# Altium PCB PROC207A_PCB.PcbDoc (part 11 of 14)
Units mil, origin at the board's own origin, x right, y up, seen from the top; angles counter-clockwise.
Board outline 4094.49 x 3724.79 mil, 8 copper layers (Top Layer, L2_GND1, L3_SIG1, L4_PWR1, L5_PWR2, L6_SIG2, L7_GND2, Bottom Layer), stack 58.1 mil thick; 584 components, 399 nets, 8440 pads, 5258 vias.
Unrouted connection lines stored in the file: 9.
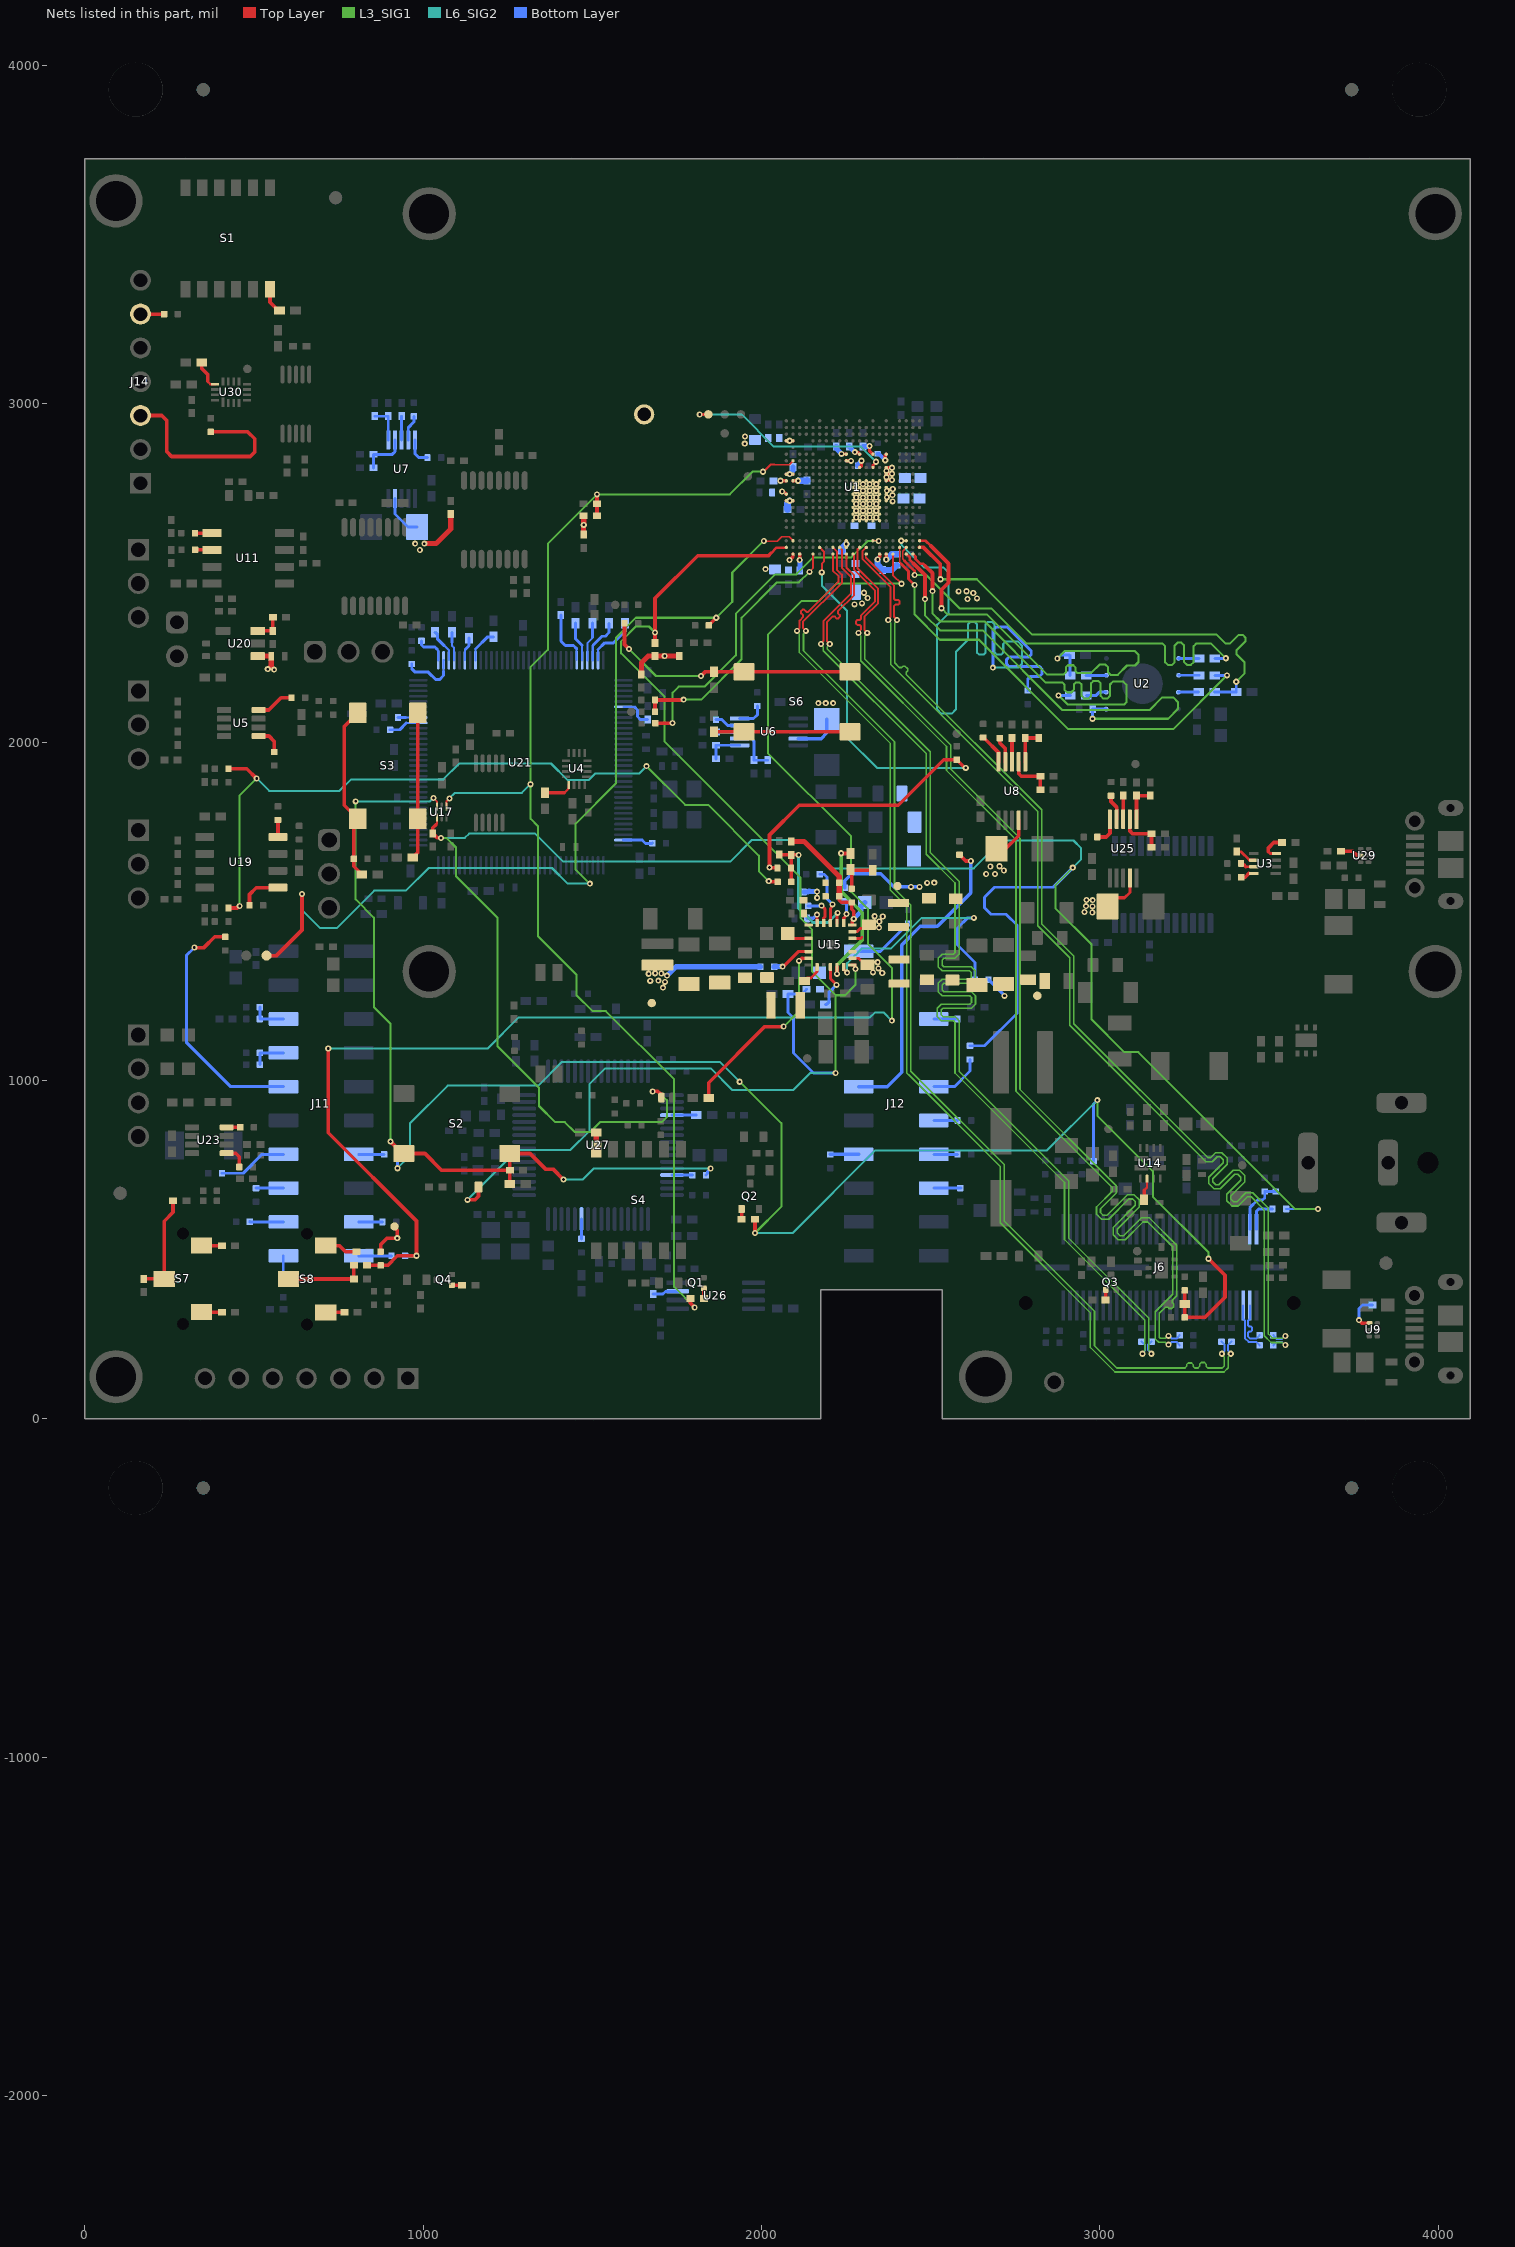
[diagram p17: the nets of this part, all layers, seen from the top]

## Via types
v1: diameter 13.77, hole 7, Top Layer to L2_GND1, tented top, 4306 vias
v2: diameter 18, hole 8, Top Layer to Bottom Layer, tented both sides, 946 vias
v3: diameter 19.68, hole 8, Top Layer to Bottom Layer, tented both sides, 6 vias

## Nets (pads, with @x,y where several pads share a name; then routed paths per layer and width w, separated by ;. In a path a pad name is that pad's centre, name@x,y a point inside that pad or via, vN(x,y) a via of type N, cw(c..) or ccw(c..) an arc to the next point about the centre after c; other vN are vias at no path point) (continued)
NetJ6_56: J6.56 R229.1 | length 151
  Bottom Layer w5.9: J6.56@3423.75,334.85 3423.75,295.66 3428.69,290.72 3428.69,238.82 3440.09,227.43 3463.01,227.43 3472.47,217.98 R229.1@3472.47,217.48
NetJ6_57: J6.57 R62.2 R153.1 | length 171.3
  Bottom Layer w8.7: J6.57@3443.44,560.44 3443.44,623.86 3466.07,646.5 3480.99,646.5 3487.69,653.2 R62.2@3487.69,672.07 R153.1@3520.34,672.07
NetJ6_58: J6.58 R230.1 | length 150.4
  Bottom Layer w5.9: J6.58@3443.44,334.85 3443.44,295.66 3438.49,290.72 3438.49,276.29 3442.3,272.48 3447.02,272.48 3450.48,269.03 3450.48,262.16 3447.02,258.7 3441.95,258.7 3438.49,255.25 3438.49,242.88 3444.15,237.23 3463.01,237.23 3472.47,246.68 R230.1@3472.47,247.17
NetJ6_59: J6.59 R63.2 | length 103.6
  Bottom Layer w8.7: J6.59@3463.12,560.44 3463.12,613.96 3469.67,620.51 R63.2@3510.52,620.51
NetJ11_5: J11.5 R176.2 R180.2 | length 105
  Bottom Layer w8.7: R180.2@517.05,1217 R176.2@517.05,1182 J11.5@587.05,1182
NetJ11_7: J11.7 R178.2 R198.2 | length 105
  Bottom Layer w8.7: R198.2@517.05,1047 R178.2@517.05,1082 J11.7@587.05,1082
NetJ11_9: J11.9 R254.2 | length 735.6
  Top Layer w10.8: v2(323.54,1393.06) 351.97,1393.06 383.64,1424.73 R254.2@414.56,1424.73
  Bottom Layer w8.7: v2(323.54,1393.06) 299.81,1369.33 299.81,1112.89 430.71,982 J11.9@587.05,982
NetJ11_13: J11.13 R210.2 | length 205.2
  Bottom Layer w8.7: R210.2@405,726 467.71,726 523.71,782 J11.13@587.05,782
NetJ11_14: J11.14 R211.1 | length 75
  Bottom Layer w8.7: J11.14@809.49,782 R211.1@884.49,782
NetJ11_15: J11.15 R222.2 | length 81.2
  Bottom Layer w8.7: R222.2@505.82,682 J11.15@587.05,682
NetJ11_17: J11.17 R224.2 | length 100.2
  Bottom Layer w8.7: R224.2@487.18,582.78 487.96,582 J11.17@587.05,582
NetJ11_18: J11.18 R232.1 | length 70
  Bottom Layer w8.7: J11.18@809.49,582 R232.1@879.49,582
NetJ11_19: J11.19 R238.2 | length 82.6
  Bottom Layer w6: J11.19@586.27,481.22 J11.19@587.05,482
  Bottom Layer w8.7: R238.2@586.27,399.73 J11.19@586.27,481.22
NetJ11_20: J11.20 R240.1 | length 96.6
  Bottom Layer w8.7: J11.20@809.49,482 R240.1@906.04,482
NetJ12_1: J12.1 R175.2 | length 180.9
  Bottom Layer w8.7: J12.1@2287.05,1382 2351.96,1382 R175.2@2433.97,1464.01
NetJ12_6: J12.6 R177.1 | length 70
  Bottom Layer w8.7: J12.6@2509.49,1182 R177.1@2579.49,1182
NetJ12_9: J12.9 R182.2 | length 925.3
  Top Layer w10.8: R182.2@2585.42,1667.27 2585.92,1667.27 2589.87,1663.32 2589.87,1662.83 2603.76,1648.94 v2(2618.76,1648.94)
  Bottom Layer w10: J12.9@2287.05,982 2372,982 2414,1024 2414,1400.75 2469.11,1455.85 2520.19,1455.85 2618.76,1554.43 v2(2618.76,1648.94)
NetJ12_10: J12.10 R183.1 | length 160.2
  Bottom Layer w8.7: J12.10@2509.49,982 2570.12,982 2616.19,1028.07 R183.1@2616.19,1062.44
NetJ12_12: J12.12 R201.1 | length 70
  Bottom Layer w8.7: J12.12@2509.49,882 R201.1@2579.49,882
NetJ12_13: J12.13 R212.2 | length 84.1
  Bottom Layer w10: R212.2@2202.92,782 J12.13@2287.05,782
NetJ12_14: J12.14 R221.1 | length 70
  Bottom Layer w8.7: J12.14@2509.49,782 R221.1@2579.49,782
NetJ12_16: J12.16 R223.1 | length 79.6
  Bottom Layer w8.7: J12.16@2509.49,682 R223.1@2589.11,682
NetJ14_3: J14.3 R285.1 | length 624.5
  Top Layer w10.8: J14.3@164.17,2965.75 226.8,2965.75 242.34,2950.2 242.34,2858.47 256.15,2844.66 488.43,2844.66 501.75,2857.98 501.75,2897.18 481.5,2917.43 R285.1@371.87,2917.43
NetJ14_6: J14.6 R286.1 | length 70
  Top Layer w10.8: J14.6@164.17,3265.75 R286.1@234.17,3265.75
NetQ1_1: Q1.1 R171.1 | length 30
  Top Layer w10.8: R171.1@1829.27,355.83 Q1.1@1829.27,385.83
NetQ2_1: Q2.1 R179.2 | length 30
  Top Layer w10.8: R179.2@1941.38,590.43 Q2.1@1941.38,620.43
NetQ3_1: Q3.1 R263.1 | length 30
  Top Layer w10.8: R263.1@3017.23,351.35 Q3.1@3017.23,381.35
NetQ4_1: Q4.1 R66.1 | length 30
  Top Layer w10.8: Q4.1@1084.87,394.98 R66.1@1114.87,394.98
NetR2_1: R2.1 R101.2 U6.2 | length 141.9
  Bottom Layer w8.7: U6.2@1935.43,2010.83 1970.16,2010.83 1978.01,2002.98 R2.1@1978.01,1946.88 R101.2@2018.01,1946.88
NetR6_2: R6.2 U4.13 | length 85.7
  Top Layer w7: 1416.83,1850.39 1430.12,1863.68 U4.13@1430.12,1874.02
  Top Layer w10.8: R6.2@1360.24,1850.39 1416.83,1850.39
NetR13_2: R13.2 R203.2 S7.2 | length 301.7
  Top Layer w10.8: R203.2@174.2,413.65 S7.2@234.2,413.65 234.2,584.26 260.32,610.38 R13.2@260.32,644.49
NetR14_1: R14.1 R103.2 U6.1 | length 110
  Bottom Layer w8.7: R103.2@1865.43,1951.15 R14.1@1865.43,1991.15 U6.1@1935.43,1991.15
NetR16_2: R16.2 R206.2 S8.2 | length 232.8
  Top Layer w10.8: S8.2@601.65,413.28 R16.2@794.44,413.28 ; R16.2@794.73,413.57 R206.2@794.73,453.57
NetR18_2: R18.2 U23.1 | length 71.7
  Top Layer w10.8: U23.1@419.13,785.14 445.72,785.14 456.19,774.67 R18.2@456.19,744.34
NetR19_2: R19.2 U23.4 | length 40
  Top Layer w10.8: U23.4@419.13,861.92 R19.2@459.13,861.92
NetR25_1: R25.1 U6.5 | length 82.9
  Bottom Layer w8.7: U6.5@1935.43,2069.89 1976.5,2069.89 1987.58,2080.97 R25.1@1987.58,2107.09
NetR29_1: R29.1 U6.4 | length 76.6
  Bottom Layer w8.7: R29.1@1865.69,2066.72 1882.8,2066.72 1899.32,2050.2 U6.4@1935.43,2050.2
NetR33_2: R33.2 U14.10 | length 66
  Top Layer w7: 3130.93,675.21 3139.35,683.63 U14.10@3139.35,709.79
  Top Layer w10.8: R33.2@3130.93,647.27 3130.93,675.21
NetR45_1: R45.1 U2.5 | length 60
  Bottom Layer w8.7: U2.5@3233.08,2248 R45.1@3293.08,2248
NetR46_2: R46.2 U2.2 | length 62.6
  Bottom Layer w8.7: R46.2@2960.1,2138.79 2989.49,2138.79 2998.7,2148 U2.2@3018.92,2148
NetR47_2: R47.2 U2.3 | length 60
  Bottom Layer w8.7: R47.2@2959.7,2198 U2.3@3019.7,2198
NetR48_1: R48.1 U2.6 | length 60
  Bottom Layer w8: U2.6@3233.08,2198 R48.1@3293.08,2198
NetR51_1: R51.1 U2.7 | length 60
  Bottom Layer w8.7: U2.7@3232.3,2148 R51.1@3292.3,2148
NetR55_1: R55.1 U3.8 | length 41.8
  Top Layer w9: 3440.42,1611.98 U3.8@3455.43,1611.98
  Top Layer w10.8: R55.1@3418.12,1601.14 3429.59,1601.14 3440.42,1611.98
NetR56_1: R56.1 U3.7 | length 42.4
  Top Layer w7: 3431.61,1631.66 U3.7@3455.43,1631.66
  Top Layer w10.8: R56.1@3417.52,1641.74 3417.52,1641.25 3421.47,1637.3 3425.98,1637.3 3431.61,1631.66
NetR70_1: R70.1 S4.12 | length 50
  Top Layer w15: S4.12@1511.51,796.87 R70.1@1511.51,846.87
NetR72_2: R72.2 U9.1 | length 114.6
  Top Layer w10.8: v2(3766.12,291.81) 3775.03,282.9 U9.1@3797.71,282.9
  Bottom Layer w8.7: v2(3766.12,291.81) 3766.12,326.34 3776.41,336.63 R72.2@3806.64,336.63
NetR76_2: R76.2 R83.1 R84.2 | length 124.6
  Top Layer w10.8: R83.1@2266.3,1566.9 2266.3,1621.21 R76.2@2263.5,1624.01 2265.96,1621.55 R84.2@2328.82,1621.55
NetR78_2: R78.2 U5.1 | length 83.8
  Top Layer w10.8: U5.1@513.63,2018.47 543.83,2018.47 559.82,2002.47 R78.2@559.82,1971.44
NetR80_2: R80.2 U5.4 | length 112.3
  Top Layer w10.8: U5.4@513.63,2095.24 543.24,2095.24 579.85,2131.85 R80.2@610.72,2131.85
NetR82_1: R82.1 R86.2 U20.3 | length 85
  Top Layer w10.8: U20.3@510.67,2329.21 R86.2@555.67,2329.21 R82.1@555.67,2369.21
NetR94_2: R94.2 U6.3 | length 70
  Bottom Layer w8.7: R94.2@1865.43,2030.52 U6.3@1935.43,2030.52
NetR104_1: R104.1 R113.2 U7.2 | length 141.9
  Bottom Layer w8.7: R104.1@852.43,2811.18 R113.2@852.43,2851.18 908.52,2851.18 916.37,2859.03 U7.2@916.37,2893.76
NetR105_1: R105.1 R114.2 U7.1 | length 110
  Bottom Layer w8.7: R114.2@856.69,2963.76 884.08,2963.76 R105.1@896.69,2963.76 U7.1@896.69,2893.76
NetR106_1: R106.1 R116.2 U8.2 | length 141.9
  Top Layer w10.8: U8.2@2760.16,1942.5 2760.16,1907.77 2768.01,1899.92 R106.1@2824.11,1899.92 R116.2@2824.11,1859.92
NetR107_1: R107.1 R117.2 U8.1 | length 110
  Top Layer w10.8: U8.1@2779.84,1942.5 R107.1@2779.84,2012.5 R117.2@2819.84,2012.5
NetR108_1: R108.1 U7.5 | length 82.9
  Bottom Layer w8.7: U7.5@975.43,2893.76 975.43,2852.7 986.51,2841.61 R108.1@1012.63,2841.61
NetR109_1: R109.1 U8.5 | length 91.3
  Top Layer w10.8: R109.1@2654.96,2013.96 2658.91,2010.01 2660.18,2010.01 2700.6,1969.59 2700.6,1943 U8.5@2701.1,1942.5
NetR110_1: R110.1 U7.4 | length 76.6
  Bottom Layer w8.7: U7.4@955.74,2893.76 955.74,2929.88 972.26,2946.39 R110.1@972.26,2963.5
NetR111_1: R111.1 U8.4 | length 76.6
  Top Layer w10.8: R111.1@2704.27,2012.24 2704.27,1998.16 2720.79,1981.65 U8.4@2720.79,1942.5
NetR112_2: R112.2 U7.3 | length 70
  Bottom Layer w8.7: U7.3@936.06,2893.76 R112.2@936.06,2963.76
NetR115_2: R115.2 U8.3 | length 70
  Top Layer w10.8: U8.3@2740.47,1942.5 R115.2@2740.47,2012.5
NetR122_1: R122.1 U21.35 | length 99.9
  Bottom Layer w6: 1075.03,2273.57 1075.87,2272.73 U21.35@1075.91,2242.47
  Bottom Layer w7: 1061.8,2286.65 1074.88,2273.57
  Bottom Layer w8.7: R122.1@1035.35,2325.03 1042.81,2317.57 1042.81,2304.49 1060.65,2286.65 1061.8,2286.65
NetR124_1: R124.1 U21.36 | length 85.2
  Bottom Layer w6: 1085.33,2294.65 1085.33,2284.76 1090.57,2279.52 1090.57,2272.77 1091.66,2271.68 U21.36@1091.66,2242.47
  Bottom Layer w8.7: 1085.33,2294.65 R124.1@1085.33,2325.03
NetR125_1: R125.1 U21.38 | length 70
  Bottom Layer w6: U21.38@1123.56,2242.87 1123.51,2242.92 1123.51,2267.78 1123.56,2267.82 1123.56,2273.49 1125.7,2275.63
  Bottom Layer w8.7: 1125.7,2275.63 1125.55,2275.78 1135.31,2285.53 R125.1@1135.31,2307.8
NetR126_1: R126.1 U21.40 | length 101.7
  Bottom Layer w6: U21.40@1154.65,2242.47 1154.65,2275.8
  Bottom Layer w8.7: 1154.65,2275.8 1190.47,2311.62 R126.1@1208.2,2311.62
NetR132_2: R132.2 U19.1 | length 124.5
  Top Layer w10.8: R132.2@486.64,1517.78 486.64,1549.98 506.79,1570.14 U19.1@570.55,1570.14
NetR135_1: R135.1 R148.2 U25.2 | length 141.9
  Top Layer w10.8: U25.2@3089.01,1772.25 3089.01,1737.53 3096.86,1729.68 R148.2@3152.96,1729.68 R135.1@3152.96,1689.68
NetR136_1: R136.1 R150.2 U25.1 | length 110
  Top Layer w10.8: U25.1@3108.69,1772.25 R136.1@3108.69,1842.25 R150.2@3148.69,1842.25
NetR137_1: R137.1 U25.5 | length 82.9
  Top Layer w10.8: R137.1@2992.75,1720.11 3018.87,1720.11 3029.95,1731.19 U25.5@3029.95,1772.25
NetR139_1: R139.1 U25.4 | length 76.6
  Top Layer w10.8: R139.1@3033.12,1841.99 3033.12,1824.88 3049.64,1808.37 U25.4@3049.64,1772.25
NetR142_2: R142.2 U25.3 | length 70
  Top Layer w10.8: U25.3@3069.32,1772.25 R142.2@3069.32,1842.25
NetR143_2: R143.2 U19.4 | length 50
  Top Layer w10.8: U19.4@570.55,1720.14 R143.2@570.55,1770.14
NetR151_2: R151.2 U3.6 | length 61
  Top Layer w8: R151.2@3404.89,1676.62 3416.64,1676.62 U3.6@3441.92,1651.35
  Top Layer w9: U3.6@3441.92,1651.35 U3.6@3455.43,1651.35
NetR159_1: R159.1 U11.6 | length 50
  Top Layer w10.8: R159.1@325.62,2568.79 U11.6@375.62,2568.79
NetR160_1: R160.1 U11.5 | length 50.7
  Top Layer w10.8: R160.1@325.13,2618.33 375.16,2618.33 U11.5@375.62,2618.79
NetR170_1: R170.1 U21.95 | length 90.3
  Bottom Layer w8: U21.95@1591.66,1710.97 1647.09,1710.97
  Bottom Layer w8.7: 1647.09,1710.97 1657.28,1700.79 1676.16,1700.79 R170.1@1677.27,1701.9
NetR181_2: R181.2 U21.33 | length 97.5
  Bottom Layer w6: 1041.14,2275 1044.41,2271.73 U21.33@1044.41,2242.47
  Bottom Layer w8.7: R181.2@994.75,2299.8 994.75,2287.95 1001.21,2281.5 1034.64,2281.5 1041.14,2275
NetR185_2: R185.2 U26.3 | length 75.6
  Bottom Layer w8.7: R185.2@1679.65,368.7 1708.36,368.7 1716.34,376.68 U26.3@1751.97,376.68
NetR188_2: R188.2 U21.34 | length 171.5
  Bottom Layer w7: 1060.16,2210.26 1060.11,2210.31 1060.11,2242.42 U21.34@1060.16,2242.47
  Bottom Layer w8.7: R188.2@966.13,2231.17 966.13,2217.65 976.5,2207.27 1015.09,2207.27 1037.42,2184.95 1047.94,2184.95 1060.16,2197.17 1060.16,2210.26
NetR190_2: R190.2 U21.25 | length 60
  Bottom Layer w6: 949.41,2073.18 U21.25@985.36,2073.18
  Bottom Layer w8.7: R190.2@925.36,2073.18 949.41,2073.18
NetR191_1: R191.1 U21.63 | length 157.2
  Bottom Layer w6: U21.63@1516.86,2242.47 1516.86,2274.16
  Bottom Layer w8.7: 1516.86,2274.16 1536.79,2294.09 1562.1,2294.09 1596.96,2328.95 R191.1@1596.96,2351.67
NetR194_1: R194.1 U21.62 | length 135.1
  Bottom Layer w6: U21.62@1501.11,2242.47 1501.11,2281.03 1501.11,2285.87 1502.71,2287.47
  Bottom Layer w8.7: 1502.71,2287.47 1528.71,2313.47 1538.72,2313.47 1549.54,2324.29 R194.1@1549.54,2351.67
NetR195_1: R195.1 U21.61 | length 115.7
  Bottom Layer w6: U21.61@1485.36,2242.47 1485.36,2293.14 1500.19,2307.97 1500.19,2309.96
  Bottom Layer w8.7: 1500.19,2309.96 R195.1@1500.19,2352.01
NetR196_1: R196.1 U21.60 | length 117.8
  Bottom Layer w6: U21.60@1469.61,2242.47 1469.61,2286.77
  Bottom Layer w8.7: R196.1@1449.62,2352.01 1449.62,2306.76 1469.61,2286.77
NetR204_1: R204.1 S7.3 | length 60
  Top Layer w10.8: S7.3@344.44,512.08 R204.1@404.44,512.08
NetR205_2: R205.2 S7.1 | length 60
  Top Layer w10.8: S7.1@344.44,315.23 R205.2@404.44,315.23
NetR207_1: R207.1 S8.3 | length 97.4
  Top Layer w10.8: S8.3@711.89,511.71 752.34,511.71 769.73,494.32 R207.1@802.12,494.32
NetR208_2: R208.2 S8.1 | length 55
  Top Layer w10.8: S8.1@711.89,314.86 R208.2@766.89,314.86
NetR213_1: R213.1 S3.1 S3.2 | length 434.2
  Top Layer w10.8: R213.1@968.7,1658.85 983.7,1673.85 S3.2@983.7,1773.85 S3.1@983.7,2086.84
NetR214_1: R214.1 R215.1 S3.3 S3.4 | length 525.4
  Top Layer w10.8: S3.3@806.54,2086.84 766.34,2046.65 766.34,1814.04 S3.4@806.54,1773.85 794.82,1762.13 R214.1@794.82,1655.53 794.82,1633.26 R215.1@818.65,1609.44
NetR231_1: R231.1 U21.70 | length 98.5
  Bottom Layer w6: U21.70@1591.66,2104.67 1623.66,2104.67
  Bottom Layer w8.7: 1623.66,2104.67 1633.27,2095.06 1633.27,2075.82 1641.49,2067.6 R231.1@1663.56,2067.6
NetR234_2: R234.2 U21.59 | length 166.9
  Bottom Layer w6: U21.59@1453.76,2242.57 1453.76,2276.2
  Bottom Layer w8.7: R234.2@1406.98,2375.95 1406.98,2298.79 1420.03,2285.74 1444.22,2285.74 1453.76,2276.2
NetR242_1: R242.1 U27.59 | length 58.6
  Bottom Layer w8.7: R242.1@1467.64,531.91 U27.59@1467.64,590.55
NetR251_1: R251.1 U27.36 | length 71.8
  Bottom Layer w8.7: U27.36@1735.35,897.64 R251.1@1807.17,897.64
NetR260_2: R260.2 U29.5 | length 64
  Top Layer w10: 3760.27,1665.25 U29.5@3771.42,1665.25
  Top Layer w10.8: R260.2@3712.48,1677.42 3748.1,1677.42 3760.27,1665.25
NetR262_1: R262.1 S6.1 S6.2 | length 401.9
  Top Layer w10.8: R262.1@1859.55,2030.85 R262.1@1859.79,2030.85 S6.2@1948.41,2030.85 S6.1@2261.4,2030.85
NetR264_1: R264.1 R265.1 S6.3 S6.4 | length 772.9
  Top Layer w10.8: R264.1@1594.9,2351.95 1594.9,2289.1 v2(1608,2276) ; v2(1821,2196) 1833.02,2208.02 S6.4@1948.41,2208.02 S6.3@2261.4,2208.02
  L3_SIG1 w6: v2(1608,2276) 1688,2196 v2(1821,2196)
NetR267_1: R267.1 R268.1 U1.U21 | length 776.9
  Top Layer w5: v2(2142.04,2503.84) 2152.21,2514.02 U1.U21@2152.21,2556.4
  Top Layer w10.8: R267.1@1685.31,2090.04 R268.1@1685.31,2125.04 1768.88,2125.04 v2(1769.81,2125.96)
  L3_SIG1 w6: v2(1769.81,2125.96) 1821.39,2125.96 1941.53,2246.1 1941.53,2368.09 2045.85,2472.41 2110.61,2472.41 v2(2142.04,2503.84)
NetR270_1: R270.1 U1.H19 | length 1025
  Top Layer w4: U1.H19@2329.38,2595.77 2329.79,2595.35 2345.98,2595.35 v2(2346.4,2594.93)
  Top Layer w10.8: R270.1@1686.12,2056.5 1736.47,2056.5 v2(1737.02,2057.05)
  L3_SIG1 w6: v2(1737.02,2057.05) 1737.02,2146.56 1754.97,2164.52 1831.52,2164.52 1924,2257 1924,2379.69 2040.74,2496.43 2102.88,2496.43 2153.03,2546.59 2265.59,2546.59 2313.93,2594.93 v2(2346.4,2594.93)
NetR272_2: R272.2 U30.13 | length 88.6
  Top Layer w7: 362.58,3066.7 370.81,3058.46 U30.13@384.62,3058.46
  Top Layer w10.8: R272.2@345.57,3122.76 345.57,3105.05 362.58,3088.04 362.58,3066.7
NetR277_1: R277.1 S1.12 | length 77
  Top Layer w10.8: S1.12@546.89,3339.18 546.89,3300.4 571.29,3276 R277.1@575,3276
NetR280_1: R280.1 U15.5 | length 119.5
  Top Layer w9: 2108.38,1381.08 U15.5@2138.7,1381.08
  Top Layer w10.8: v2(2062.38,1336.65) 2063.94,1336.65 2108.38,1381.08
  Bottom Layer w15: R280.1@2037.62,1336.5 2037.69,1336.58 2062.3,1336.58 v2(2062.38,1336.65)
NetR281_1: R281.1 U15.20 | length 67.6
  Top Layer w9: U15.20@2243.03,1467.26 2243.03,1480.04 2249.21,1486.22 2249.21,1490.67 v2(2250.93,1492.39)
  Bottom Layer w9: R281.1@2246.12,1529.61 2250.93,1524.79 v2(2250.93,1492.39)
NetR282_1: R282.1 U15.12 | length 714.2
  Top Layer w8: U15.12@2243.03,1335.81 2243.03,1328.92 2252.87,1319.08 v2(2253.17,1319.08)
  L6_SIG2 w6: v2(2253.17,1319.08) 2253.17,1347.05 2295.9,1389.78 2382.52,1389.78 2473.81,1481.07 v2(2627.53,1481.07)
  Bottom Layer w8.7: v2(2627.53,1481.07) 2609.41,1481.07 2579.47,1451.13 2579.47,1400.62 2630.74,1349.34 R282.1@2630.74,1297.66
NetR283_2: R283.2 U3.4 | length 84.6
  Top Layer w8: 3498.42,1676.47 3503.86,1671.03 U3.4@3522.36,1671.03
  Top Layer w10.8: 3498.42,1676.47 3498.42,1687.59 3514.31,1703.48 R283.2@3539.15,1703.48
NetR284_2: R284.2 U1.C19 | length 2128.1
  Top Layer w4: v2@2413.18,2595.78 U1.C19@2427.8,2595.77
  L6_SIG2 w6: v2(2413.17,2595.8) 2413.17,2583.78 2479.92,2517.02 2536.83,2517.02 2553.04,2500.81 2553.04,2381.46 2519.39,2347.82 2519.39,2096.88 2531.7,2084.58 2562.07,2084.58 2575,2097.5 2575,2268.14 2610.62,2303.77 2610.62,2348.98 2617.12,2355.48 2630.12,2355.48 2636.62,2348.98 2636.62,2265.31 2643.12,2258.81 2656.12,2258.81 2662.62,2265.31 2662.62,2348.98 2669.12,2355.48 2682.12,2355.48 2688.62,2348.98 2688.62,2265.31 2695.12,2258.81 2708.12,2258.81 2714.62,2265.31 2714.62,2290.77 2721.12,2297.27 2758.73,2297.27 2769.84,2286.16 2769.84,2231.39 2758.92,2220.47 v2(2683.98,2220.47)
  Bottom Layer w8.7: v2(2683.98,2220.47) 2683.98,2330.94 2693.78,2340.74 2726.26,2340.74 2797.43,2269.57 2797.43,2259.43 2790.25,2252.25 2731.84,2252.25 2724.66,2245.08 2724.66,2230.73 2731.84,2223.55 2822.17,2223.55 2829.29,2216.43 2829.29,2202.08 2822.07,2194.85 2795.87,2194.85 2787,2185.98 R284.2@2787,2153.18
NetR290_2: R290.2 U21.24 | length 91.6
  Bottom Layer w6: 950.87,2057.43 U21.24@985.36,2057.43
  Bottom Layer w8.7: R290.2@902.18,2037 930.44,2037 950.87,2057.43
NRST_FTDI: R243.1 U27.45 | length 60
  Bottom Layer w8.7: U27.45@1735.35,720.47 R243.1@1795.35,720.47
PGOOD: R58.1 R91.1 R92.2 R179.1 R211.2 R241.1 | length 4157.1
  Top Layer w10.8: R179.1@1980.75,590.43 1980.8,590.37 v2(1980.86,549.47) v2(1980.86,549.47) ; R241.1@3251.09,379.25 3251.09,378.58 3251.04,378.52 R92.2@3251.04,339.8 R91.1@3251.04,299.8 3310.2,299.8 3370.19,359.78 3370.19,424.76 3323.94,471.01 3323.6,471.01 v2(3321.42,473.18)
  L3_SIG1 w6: v2(1935.31,996.43) 1935.93,996.43 2058.54,873.82 2058.54,627.16 v2(1980.86,549.47) ; v2(2992.63,942.09) 2992.63,896.42 3157.06,731.99 3157.06,656.37 3321.42,492.01 v2(3321.42,473.18)
  L6_SIG2 w6: v2(923.76,740.77) 961,778 961,873.86 1072.04,984.9 1340.2,984.9 1410.26,1054.96 1876.77,1054.96 v2(1935.31,996.43) ; v2(1980.86,549.47) 2092.25,549.47 2336.27,793.49 2844.03,793.49 v2(2992.63,942.09)
  Bottom Layer w8.7: v2(923.76,740.77) 924.3,741.31 924.3,781.46 R211.2@924.84,782 ; R58.1@2981.57,761.67 2981.57,931.03 v2(2992.63,942.09)
PMIC_B1_SW: C69.2 L5.1 U15.8 | length 59.9
  Top Layer w9: C69.2@2127.82,1295.94 2134.99,1303.11 2146.07,1303.11 2164.29,1321.33 U15.8@2164.29,1334.27
PMIC_B2_SW: L11.1 U15.17 | length 30.3
  Top Layer w9: U15.17@2268.62,1420.45 2293.23,1420.45 2297.25,1424.47
PMIC_B3_SW: L6.1 U15.15
PMIC_CAN_STB_CTRL: R85.1 R131.1 R273.1 | length 2322.9
  Top Layer w10.8: R131.1@424.37,1510.14 449.69,1510.14 455.48,1515.94 v2(457.43,1515.94) ; R273.1@424.54,1921.85 478.69,1921.85 v2(507.46,1893.08) ; v2(2021.49,1589.4) 2023.44,1589.4 2025.61,1587.23 R85.1@2047.68,1587.23
  L3_SIG1 w6: v2(457.43,1515.94) 457.43,1843.05 v2(507.46,1893.08) ; v2(1659.92,1929.34) 1774.27,1815 1841.95,1815 1992.06,1664.89 1992.06,1618.83 v2(2021.49,1589.4)
  L6_SIG2 w6: v2(507.46,1893.08) 544.44,1856.1 752.51,1856.1 786.78,1890.36 1059.43,1890.36 1106.3,1937.23 1377.73,1937.23 1426.18,1888.78 1490.16,1888.78 1508.93,1907.55 1638.13,1907.55 v2(1659.92,1929.34)
PMIC_CLKOUT: R15.2 TP1.1 | length 116
  Top Layer w10.8: R15.2@874.1,493.92 874.1,515.19 892.93,534.02 v2(923.17,534.02) 923.17,556.78 915.24,564.72 TP1.1@915.24,568.56
PMIC_CLKOUT_SOP1: R15.1 R206.1 R240.2 U1.E21 | length 4480.8
  Top Layer w6: U1.E21@2388.43,2556.4 2388.43,2494.28 v2(2414.06,2468.64)
  Top Layer w10.8: v2(719.21,1094.85) 719.21,845.79 980.04,584.96 v2(980.04,482) 923.28,482 894.85,453.57 R206.1@834.1,453.57
  L3_SIG1 w6: v2(2385.18,1177.15) 2385.13,1177.19 2385.13,1333.33 2314.31,1404.15 2314.31,1508.45 2264.73,1558.03 2264.73,1721.69 2019,1967.42 2019,2317.72 2119.28,2418 2170.64,2418 2221.28,2468.64 v2(2414.06,2468.64)
  L6_SIG2 w6: v2(719.21,1094.85) 1190.27,1094.85 1281.94,1186.51 2320.74,1186.51 2335.86,1201.63 2360.7,1201.63 v2(2385.18,1177.15)
  Bottom Layer w10.8: R240.2@946.39,482 v2(980.04,482)
PMIC_EN: R145.1 U15.10 | length 133.8
  Top Layer w9: U15.10@2203.66,1335.81 2203.66,1301.01 v2(2221.73,1282.94)
  Bottom Layer w9: R145.1@2189.02,1225.21 2192.69,1225.21 2200,1232.52 2200,1261.21 v2(2221.73,1282.94)
PMIC_LS_3V3: C87.1 L14.1 R77.1 U15.1
PMIC_nINT_GPIO: R54.1 R57.2 R85.2 R245.2 U15.21 | length 471.9
  Top Layer w9: U15.21@2223.34,1465.73 2223.34,1488.36 2223.44,1488.45 2223.44,1491.68 2225.16,1493.4 v2(2225.16,1495.84)
  Top Layer w10.8: R57.2@2052.42,1668.18 2053.42,1667.18 R54.1@2087.42,1667.18 2087.56,1667.03 2109.61,1667.03 v2(2109.75,1666.89) ; R85.2@2088.03,1587.23 2088.03,1627.56 R245.2@2087.42,1628.18 2088.21,1628.97 R54.1@2088.21,1667.38
  L6_SIG2 w8: v2(2109.75,1666.89) 2109.57,1666.71 2109.57,1509.37 2151.64,1467.3 2196.61,1467.3 v2(2225.16,1495.84)
PMIC_NRST_OUT: R87.1 U15.6 | length 578
  Top Layer w9: 2121.06,1361.4 U15.6@2137.16,1361.4
  Top Layer w10.8: R87.1@1844.04,948.53 1844.04,993.68 2009.84,1159.48 v2(2065.42,1159.48) ; v2(2110.7,1354) 2112.17,1354 2119.57,1361.4 2121.06,1361.4
  L3_SIG1 w6: v2(2065.42,1159.48) 2110.7,1204.76 v2(2110.7,1354)
PMIC_OUT_1V2: C76.1 C89.1 C90.1 C156.2 FB2.1 FB3.1 L6.2 R282.2 TP19.1 | length 68.9
  Bottom Layer w10: R282.2@2669.68,1299.07 v2(2718.41,1250.34)
PMIC_OUT_1V8: C80.1 C81.1 C83.1 C155.2 FB1.1 L11.2 R281.2 TP18.1 | length 265.9
  Bottom Layer w10: R281.2@2246.12,1569.96 2246.12,1590.44 2266.69,1611 2352.33,1611 2390.64,1572.69 v2(2442.02,1572.69) v2(2467.15,1572.69)
  other v2: 2489.64,1584.29 2510.72,1584.85
PMIC_OUT_3V3: C51.1 C70.1 C71.1 C75.2 C77.2 C78.2 C79.1 C117.2 L4.1 L5.2 R278.2 R279.1 R280.2 TP16.1 U15.14 U15.18 U15.24 U20.1 | length 521.2
  Top Layer w8: U15.14@2270.15,1361.4 2286.81,1361.4 2292.32,1355.89 ; U15.18@2270.15,1440.14 2283.09,1440.14 2293.29,1450.33 2293.93,1450.33
  Top Layer w9: v2(2164.21,1490.42) v2(2164.21,1490.42) 2164.25,1473.04 2164.29,1473 U15.24@2164.29,1467.26
  Top Layer w15: U20.1@510.67,2254.41 C51.1@550.67,2254.41 550.67,2226.44 v2(540.31,2216.08)
  Bottom Layer w10: C79.1@2134.73,1479.72 2153.51,1479.72 v2(2164.21,1490.42)
  Bottom Layer w15: v2(1720.75,1310.03) 1747.23,1336.5 R280.2@1997.26,1336.5 ; R279.1@2125.1,1557.72 2136.77,1557.72 2139.97,1560.91 2141.77,1560.91 2144.28,1558.41 2164.06,1558.41 v2(2164.21,1558.26)
  other v2: 1708.79,1274.76 1714.92,1291.83 1671.01,1294.75 1695.03,1295.36 1666.39,1315.75 1685.68,1317.16 1703.76,1316.36 2356.9,1317.84 2329.5,1319.84 2346.05,1331.8 2343.35,1349.66 2347.44,1452.1 2348.14,1470.41 2358.34,1485.25 2334.47,1485.69 2164.39,1540.26 559.34,2214.62
PMIC_RADAR_nINT: R245.1 R257.1 U1.T20 | length 1785.8
  Top Layer w6: U1.T20@2171.89,2576.08 2184.05,2563.92 2184.05,2534.01 2178.14,2528.1 v2(2178.14,2502.21)
  Top Layer w10.8: R245.1@2047.06,1628.18 2046.37,1628.87 2024.06,1628.87 v2(2023.4,1629.52) 2023.4,1725.86 2111.63,1814.08 2404.27,1814.08 2538.49,1948.29 R257.1@2576.93,1948.29 ; R257.1@2581.38,1943.85 2599.32,1925.91 2602.48,1925.91 v2(2603.85,1924.53)
  L6_SIG2 w6: v2(2178.14,2502.21) 2178.14,2463.52 2252.05,2389.61 2252.05,2013.95 2341.47,1924.53 v2(2603.85,1924.53)
PMIC_SCL: R89.2 U15.23 | length 95.8
  Top Layer w9: v2(2177.25,1516.96) 2188.17,1506.04 2188.17,1484.64 2183.89,1480.36 U15.23@2183.89,1466.36
  Bottom Layer w8.7: R89.2@2137.87,1516.47 v2@2176.76,1516.47
PMIC_SDA: R90.2 U15.22 | length 169.8
  Top Layer w9: U15.22@2203.66,1465.73 2203.66,1508.96 2208.59,1513.89 2208.59,1519.52 v2(2209.96,1520.9)
  Bottom Layer w8.7: R90.2@2172.27,1609.83 2184.99,1609.83 2193.27,1601.54 2193.27,1537.59 v2(2209.96,1520.9)
PMIC_VDD_1V8: C73.1 U15.3 | length 66.7
  Top Layer w9: C73.1@2077.95,1434.71 2092.21,1420.45 U15.3@2138.7,1420.45
PMIC_VIO_3V3: C100.1 R54.2 R77.2 R83.2 R278.1 U15.19 | length 426.9
  Top Layer w10: R278.1@2229.81,1544.82 2229.81,1532.32 2235.57,1526.55 R83.2@2266.3,1526.55 2266.3,1506.63 2272.66,1500.28 v2(2272.66,1478.11) ; U15.19@2268.13,1459.82 2268.13,1471.42 2271.42,1474.71 v2@2271.42,1478.11
  Top Layer w15: R54.2@2087.42,1706.55 2126.09,1706.55 2229.75,1602.89 R77.2@2229.75,1584.85 ; R278.1@2229.81,1544.82 R77.2@2229.81,1584.62
  Bottom Layer w15: v2(2272.66,1478.11) 2293.32,1498.78 2293.32,1514.07 C100.1@2305.48,1526.22
PMIC_VREG_5V0: C88.2 R76.1 R288.2 U15.11 | length 461.9
  Top Layer w10.8: v2(2223.16,1315.51) 2223.25,1315.6 2223.25,1335.71 U15.11@2223.34,1335.81 ; v2(2235.46,1671.96) 2236.17,1671.25 R76.1@2263.5,1671.25
  L3_SIG1 w10.8: v2(2223.16,1315.51) 2223.16,1340.88 2297.82,1415.55 2297.82,1496.15 2235.46,1558.52 v2(2235.46,1671.96)
QSPI_D0: R45.2 U1.C20 | length 1377.2
  Top Layer w4: 2422.47,2536.47 2416.88,2542.06 2416.88,2565.16 U1.C20@2427.8,2576.08
  Top Layer w8: 2422.47,2536.47 2452.72,2506.22 v2(2452.72,2494.36)
  L3_SIG1 w6: v2(2452.72,2494.36) 2487.05,2494.36 2501,2480.41 2585.38,2396.04 2678.63,2396.04 2782.07,2292.59 3185,2292.59 3193.4,2284.19 3193.4,2236.25 3201.8,2227.85 3213,2227.85 3221.4,2236.25 3221.4,2286.09 3229.8,2294.49 3241,2294.49 3249.4,2286.09 3249.4,2236.94 3257.8,2228.54 3269,2228.54 3277.4,2236.94 3277.4,2284.19 3285.8,2292.59 3328.33,2292.59 v2(3372.51,2248.41)
  Bottom Layer w8.7: R45.2@3340.32,2248 3372.1,2248 v2(3372.51,2248.41)
QSPI_D1: R46.1 U1.B21 | length 1376.1
  Top Layer w8: U1.B21@2447.49,2556.4 2454.91,2548.97 2454.91,2542.04 2468.88,2528.06 2477.41,2528.06 2484.36,2521.11
  Top Layer w10.8: 2484.36,2521.11 2505.37,2500.1 v2(2505.37,2446.55)
  L3_SIG1 w6: v2(2505.37,2446.55) 2504.92,2446.1 2504.92,2381.08 2529,2357 2659.32,2357 2840.32,2176 2890.01,2176 2895.27,2170.74 2895.27,2155.54 2903.67,2147.14 2914.87,2147.14 2923.27,2155.54 2923.27,2170.74 2928.87,2176.35 2940.62,2176.35 2946.23,2170.74 2946.23,2137.54 2954.63,2129.14 2965.83,2129.14 2974.23,2137.54 2974.23,2174.84 2980.19,2180.8 2996.27,2180.8 3002.23,2174.84 3002.23,2137.54 3010.63,2129.14 3021.83,2129.14 3030.23,2137.54 3030.23,2170.74 3038.63,2179.14 3069.9,2179.14 3078.7,2170.34 3078.7,2118.29 3072.07,2111.66 2904.66,2111.66 v2(2877.91,2138.41)
  Bottom Layer w8.7: v2(2877.91,2138.41) 2878.29,2138.79 R46.1@2912.85,2138.79
QSPI_D2: R44.1 R47.1 U1.A19 | length 1377.1
  Top Layer w8: U1.A19@2467.17,2595.77 2485.37,2595.77 2501,2580.13
  Top Layer w10.8: 2501,2580.13 2552.97,2528.16 2552.97,2471.82 2532.25,2451.09 v2(2532.25,2396.22)
  L3_SIG1 w6: v2(2532.25,2396.22) 2550.93,2377.54 2666.97,2377.54 2843.76,2200.75 2894.02,2200.75 2899.68,2206.4 2899.68,2221.6 2905.74,2227.66 2921.62,2227.66 2927.68,2221.6 2927.68,2210.65 2933.39,2204.94 2974.53,2204.94 2999.59,2230 3016.29,2230 3024.69,2221.6 3024.69,2206.4 3031.55,2199.54 3053.18,2199.54 3080.52,2226.88 3104.1,2226.88 3114.43,2237.21 3114.43,2258.72 3103.37,2269.77 2896.91,2269.77 v2(2874.6,2247.45)
  Bottom Layer w8.7: v2(2874.6,2247.45) 2885.1,2257.96 R44.1@2910.49,2257.96 2912.46,2255.99 R47.1@2912.46,2198
QSPI_D3: R49.1 R51.2 U1.A20 | length 1377.3
  Top Layer w10.8: U1.A20@2467.17,2576.08 2478.7,2576.08 2528.88,2525.91 v2(2528.88,2481.88)
  L3_SIG1 w6: v2(2528.88,2481.88) 2636.31,2481.88 2799.11,2319.07 3344.72,2319.07 3372.52,2291.28 3384.4,2291.28 3410.7,2317.58 3422.58,2317.58 3430.5,2309.66 3430.5,2297.78 3404.2,2271.48 3404.2,2259.6 3427.91,2235.88 3427.91,2203.46 v2(3403.35,2178.9)
  Bottom Layer w8.7: R51.2@3339.54,2148 R49.1@3402.88,2148 3403.35,2148.48 v2(3403.35,2178.9)
QSPI_nCS: R50.2 U1.C21 U2.1 | length 1442.5
  Top Layer w8: U1.C21@2427.8,2556.4 2438.53,2545.67 2438.53,2538.81 2449.24,2528.1
  Top Layer w10.8: 2449.51,2528.38 2483.3,2494.59 v2(2483.3,2423.02)
  L3_SIG1 w6: v2(2483.3,2423.02) 2482.98,2422.7 2482.98,2375.96 2528.07,2330.87 2653.79,2330.87 2889.24,2095.41 3147.41,2095.41 3184.53,2132.53 3216.9,2132.53 3231.27,2118.16 3231.27,2098.59 3202.16,2069.47 v2(2978.62,2069.47)
  Bottom Layer w8.7: v2(2978.62,2069.47) 2978.92,2069.78 R50.2@2978.92,2098 U2.1@3018.92,2098
QSPI_SCLK: R48.2 U1.D20 | length 1382.2
  Top Layer w4: U1.D20@2408.12,2576.08 2408.12,2531.86 2413.04,2526.93
  Top Layer w8: 2413.04,2526.93 2434.43,2505.54 2434.43,2483.05 v2(2452.66,2464.82)
  L3_SIG1 w6: v2(2452.66,2464.82) 2452.66,2377.59 2527.25,2303 2643,2303 2907,2039 3217.1,2039 v2(3376.04,2197.94)
  Bottom Layer w8.7: R48.2@3340.32,2198 3375.98,2198 v2(3376.04,2197.94)
RADAR_1P2_RF: C24.2 C44.1 R134.2 U1.F11 U1.F12 U1.F13 U25.9 | length 125.7
  Top Layer w9: R134.2@3023.29,1514.68 3049.03,1540.42 3073.25,1540.42 3089.01,1556.18 U25.9@3089.01,1599.03
  other v2: 2978.02,1496.86 2954.88,1498.05 2978.34,1514.86 2959.49,1515.44 2960.94,1533.43 2979.01,1533.31 2609,2423.32 2637,2425.32 2626,2441.32 2582.83,2446.13 2606,2446.32 2387.72,2712.22 2370.54,2723.95 2387.35,2730.4 2370.43,2743.93 2387.87,2748.39
RADAR_1V2: C2.2 C25.2 C26.2 C45.2 C121.2 C128.1 C130.1 C131.2 R193.2 U1.AA9 U1.AA13 U1.G10 U1.G11 U1.G12 U1.G13 U1.G14 U1.G15 U1.G16 U1.H10 U1.H11 U1.H12 U1.H13 U1.H14 U1.H15 U1.H16 U1.J10 U1.J11 U1.J12 U1.J13 U1.J14 U1.J15 U1.J16 U1.K10 U1.K11 U1.K12 U1.K13 U1.K14 U1.K15 U1.K16 U1.L10 U1.L11 U1.L12 U1.L13 U1.L14 U1.L15 U1.L16 U1.Y9 U1.Y10 U1.Y13 U8.9 | length 261.8
  Top Layer w10: U1.AA13@2073.47,2713.88 v2(2083.31,2713.88) U1.Y13@2093.15,2713.88 ; U1.AA9@2073.47,2792.62 v2(2083.31,2792.62) U1.Y9@2093.15,2792.62 ; U1.Y10@2093.15,2772.93 v2(2108.38,2772.93)
  Top Layer w11: R193.2@2694.44,1684.93 2721.61,1684.93 2760.16,1723.48 U8.9@2760.16,1769.27
  Bottom Layer w15: v2(2083.31,2792.62) 2093.31,2802.62 C130.1@2093.31,2813.21
  Bottom Layer w20: C26.2@2076.51,2688.23 2076.51,2707.07 v2(2083.31,2713.88) ; v2(2108.38,2772.93) 2134.19,2772.93 C25.2@2134.66,2773.41
  other v2: 2663.93,1610.31 2690.12,1610.31 2716.24,1620.86 2676.5,1632.99 2703.35,1633.42 2275.07,2407.6 2297.28,2410.64 2313.64,2426.74 2302.88,2441.88 2280.16,2664.66 2299.85,2664.66 2319.53,2664.66 2339.22,2664.66 2280.16,2684.35 2299.85,2684.35 2319.53,2684.35 2339.22,2684.35 2280.16,2704.03 2299.85,2704.03 2319.53,2704.03 2339.22,2704.03 2280.16,2723.72 2299.85,2723.72 2319.53,2723.72 2339.22,2723.72 2280.16,2743.4 2299.85,2743.4 2319.53,2743.4 2339.22,2743.4 2280.16,2763.09 2299.85,2763.09 2319.53,2763.09 2339.22,2763.09
RADAR_1V4_APLL: C22.2 U1.K8 | length 41.6
  Top Layer w10: U1.K8@2290.01,2812.3 2295.67,2817.96 2295.67,2831.9 v2(2295.35,2832.22)
  Bottom Layer w15: C22.2@2284.39,2817.59 2284.39,2819.56 2294.78,2829.95 2294.78,2831.64 v2(2295.35,2832.22)
RADAR_1V4_SYNTH: C18.2 U1.F6 | length 49.5
  Top Layer w10: v2(2365.7,2833.69) 2365.7,2848.62 U1.F6@2368.75,2851.67
  Bottom Layer w12: C18.2@2343.24,2852.58 2346.81,2852.58 v2(2365.7,2833.69)
RADAR_1V8: C1.2 C4.2 C5.2 C7.2 C8.2 C10.2 C11.2 C12.2 C13.1 C14.2 C15.1 R192.2 U1.AA4 U1.AA10 U1.F21 U1.H6 U1.K6 U1.M6 U1.M19 U1.M20 U1.Y4 U1.Y21 U6.9 | length 422.4
  Top Layer w10: v2(2056.24,2772.93) U1.AA10@2073.47,2772.93 ; U1.AA4@2073.47,2891.04 U1.Y4@2093.15,2891.04 ; v2@2083.07,2539.04 2093.15,2549.13 U1.Y21@2093.15,2556.4 ; v2(2236.74,2852.6) 2237.32,2852.02 2250.28,2852.02 U1.M6@2250.64,2851.67 ; U1.M20@2250.64,2576.08 v2(2250.64,2585.92) U1.M19@2250.64,2595.77 ; v2(2275.95,2857.47) 2277.48,2855.94 2285.74,2855.94 U1.K6@2290.01,2851.67 ; v2(2319.15,2875.49) 2319.15,2861.89 U1.H6@2329.38,2851.67 ; v2(2368.75,2540.02) U1.F21@2368.75,2556.4
  Bottom Layer w10: U6.9@2108.66,2010.83 2176.34,2010.83 2193,2027.49 R192.2@2193,2068.91
  Bottom Layer w15: C4.2@2220.86,2874.86 2220.86,2868.48 v2(2236.74,2852.6) ; C5.2@2259.47,2874.69 2259.47,2873.95 v2(2275.95,2857.47) ; C14.2@2299.96,2874.86 2318.52,2874.86 v2(2319.15,2875.49)
  Bottom Layer w18: v2(2368.75,2540.02) 2384.74,2556.01 C10.2@2399.75,2556.01
  Bottom Layer w20: C1.2@2238.25,2564.55 2238.25,2573.54 v2(2250.64,2585.92)
  other v2: 2168.03,2115.49 2189.86,2115.49 2211.69,2115.49 2011.73,2511.86 2082.84,2539.04 1950.36,2882.75 2083.31,2891.33 1951.22,2903.75
RADAR_1V_RF_OUT: C9.2 C19.2 TP22.1 U1.F8 U1.F9 U1.F10 U1.M7 | length 65.1
  Top Layer w10: U1.M7@2250.64,2831.99 v2(2264.55,2831.99) ; U1.F10@2368.75,2772.93 2371.75,2775.93 v2@2385.14,2775.93 ; U1.F9@2368.75,2792.62 2370.29,2794.16 v2@2385.38,2794.16 ; U1.F8@2368.75,2812.3 2384.58,2812.3 v2@2384.9,2811.98
  other v2: 2385.88,2775.53 2369.58,2783.51 2385.88,2793.76 2369.72,2802.4 2385.88,2811.58
RADAR_3V3: C16.2 C17.2 C21.2 R146.2 R200.2 R246.2 R247.2 R250.2 R255.2 R256.2 R261.1 U1.AA12 U1.G21 U1.W21 U7.9 | length 644.3
  Top Layer w10: v2(2061.07,2741.16) 2065.87,2741.16 U1.AA12@2073.47,2733.56 ; v2@2112.46,2539.04 2112.84,2539.41 U1.W21@2112.84,2556.4 ; v2(2343.39,2540.02) 2343.39,2542.72 2349.06,2548.39 U1.G21@2349.06,2556.4
  Top Layer w15: v2(1003.18,2587.04) 1037.78,2587.04 1081.26,2630.52 R256.2@1081.26,2674.5 ; R255.2@1474.36,2614.11 v2@1474.36,2642.64 ; v2(1474.49,2642.78) R250.2@1474.49,2669.49 ; R146.2@1644.95,2201 1644.95,2235.19 1664.34,2254.58 v2@1713.42,2254.58 ; v2(1713.56,2254.72) R261.1@1757.13,2254.72
  Bottom Layer w9: U7.9@916.37,2720.53 916.37,2674.74 954.92,2636.19 R200.2@982.09,2636.19
  Bottom Layer w15: v2(2112.84,2539.04) 2113.38,2538.5 C21.2@2113.38,2508.1
  Bottom Layer w18: v2(2343.39,2540.02) 2343.39,2524.25 C16.2@2358.5,2509.14 2385.56,2509.14 R246.2@2399.75,2523.33
  other v2: 990.07,2568.12 976.29,2587.04
RADAR_LVDS_0M: R230.2 U1.J21 | length 3238.3
  Top Layer w5.8: U1.J21@2309.69,2556.4 2308.17,2554.87 2308.17,2546.15 2391.97,2462.34 2391.97,2423.94 2395.42,2420.49 2404.88,2420.49 2408.3,2417.07 2408.3,2410.17 2404.83,2406.69 2395.42,2406.69 2391.97,2403.24 2391.97,2370.33 v2(2400.61,2361.7)
  L3_SIG1 w4.8: 2393.62,2352.27 2393.62,2234.92 2407.6,2220.94 2414.39,2220.94 2418,2224.55 2424.41,2224.55 2431.97,2216.99 2431.97,2211.36 2427.96,2207.36 2427.96,2200.57 2828.32,1800.22 2828.32,1462.66 2923,1367.97 2923,1168.22 3318.86,772.36 3327.62,772.36 3342.17,786.9 3360.88,786.9 3376.68,771.11 3376.68,752.4 3333.85,709.57 3333.85,700.8 3342.62,692.03 3351.38,692.03 3394.21,734.86 3412.92,734.86 3428.72,719.06 3428.72,700.35 3387.12,658.76 3387.12,649.99 3395.89,641.22 3404.66,641.22 3431.71,668.27 3452.41,668.27 3498.49,622.19 3498.49,250.57 3511.36,237.71 3539.4,237.71 3546.66,244.97 v2(3548.39,244.97) ; 2393.61,2352.28 2400.61,2359.28 v2(2400.61,2361.7)
  Bottom Layer w5.9: R230.2@3512.82,247.17 3512.82,246.68 3522.89,236.61 3538.35,236.61 3546.71,244.97 v2(3548.39,244.97)
RADAR_LVDS_0P: R229.2 U1.J20 | length 3238.2
  Top Layer w5.8: U1.J20@2309.69,2576.08 2298.17,2564.56 2298.17,2542 2381.97,2458.2 2381.97,2370.59 2374.61,2363.23 v2(2374.61,2361.7)
  L3_SIG1 w4.8: v2(2374.61,2361.7) 2374.61,2359.28 2381.61,2352.28 2381.61,2229.96 2816.32,1795.25 2816.32,1457.68 2911,1363 2911,1163.24 3313.89,760.36 3332.6,760.36 3347.14,774.9 3355.91,774.9 3364.68,766.14 3364.68,757.37 3321.85,714.54 3321.85,695.83 3337.64,680.03 3356.35,680.03 3399.18,722.86 3407.95,722.86 3416.72,714.09 3416.72,705.33 3375.12,663.73 3375.12,645.02 3390.92,629.22 3409.63,629.22 3436.68,656.27 3447.44,656.27 3486.49,617.22 3486.49,245.6 3506.39,225.71 3538.98,225.71 3546.25,218.44 v2(3548.39,218.44)
  Bottom Layer w5.9: R229.2@3512.82,217.48 3512.82,217.98 3521.65,226.81 3538.35,226.81 3546.71,218.44 v2(3548.39,218.44)
RADAR_LVDS_1M: R228.2 U1.P21 | length 3317.4
  Top Layer w5.8: v2(2105.1,2329.45) 2105.1,2331.58 2112.46,2338.95 ; 2112.46,2339 2112.46,2359.82 2123.22,2370.58 2123.22,2375.46 2116.53,2382.15 2116.53,2386.99 2121.41,2391.87 2126.33,2391.87 2132.98,2385.22 2137.86,2385.22 2227,2474.36 2227,2491.55 2211.27,2507.29 U1.P21@2211.27,2556.4
  L3_SIG1 w4.8: v2(2105.1,2329.45) 2105.1,2327.04 2112.1,2320.04 2112.1,2265.53 2381,1996.63 2381,1562.4 2429.53,1513.86 2429.53,1022.32 2436.56,1015.29 2706,745.86 2706,579.4 2713.03,572.37 2972.24,313.16 2972.24,210.87 3044.75,138.36 3367.27,138.36 3379.92,151.01 3379.92,183.08 3387.19,190.34 v2(3387.19,192.49)
  Bottom Layer w5.9: v2(3387.19,192.49) 3387.19,194.17 3378.82,202.54 3378.82,218 3388.89,228.06 R228.2@3389.38,228.06
RADAR_LVDS_1P: R227.2 U1.P20 | length 3316.5
  Top Layer w5.8: v2(2131.1,2329.45) 2131.1,2330.37 2122.46,2339 2122.46,2355.68 2237.5,2470.72 2237.5,2495.48 2222.94,2510.04 2222.94,2564.41 U1.P20@2211.27,2576.08
  L3_SIG1 w4.8: v2(2131.1,2329.45) 2131.1,2327.04 2124.1,2320.04 2124.1,2270.5 2393,2001.6 2393,1567.37 2441.53,1518.83 2441.53,1027.29 2718,750.83 2718,584.37 2984.24,318.13 2984.24,215.84 3049.72,150.36 3251.73,150.36 3256.53,155.16 3256.53,160.36 3261.33,165.16 3270.93,165.16 3275.73,160.36 3275.73,155.16 3280.53,150.36 3290.13,150.36 3294.93,155.16 3294.93,161.56 3299.73,166.36 3309.33,166.36 3314.13,161.56 3314.13,155.16 3318.93,150.36 3362.3,150.36 3367.92,155.98 3367.92,183.08 3360.66,190.34 v2(3360.66,192.49)
  Bottom Layer w5.9: R227.2@3359.7,228.06 3360.19,228.06 3369.02,219.23 3369.02,200.85 v2(3360.66,192.49)
RADAR_LVDS_CLKM: R226.2 U1.L21 | length 3238.1
  Top Layer w5.8: U1.L21@2270.32,2556.4 2273.76,2552.96 2273.76,2510.44 2335.03,2449.17 2335.03,2415.61 2294,2374.58 2294,2364.36 2290.55,2360.91 2282.69,2360.91 2279.29,2357.51 2279.29,2350.99 2283.18,2347.11 2290.55,2347.11 2294,2343.66 2294,2333.26 ; v2(2286.63,2323.45) 2286.63,2325.59 2294,2332.95
  L3_SIG1 w4.8: v2(2286.63,2323.45) 2286.63,2321.04 2293.63,2314.04 2293.63,2240.72 2546.9,1987.45 2546.9,1916.83 2752.23,1711.5 2752.23,968.8 3036.9,684.13 3036.9,672.75 2990.18,626.03 2990.18,604.72 3004.79,590.11 3026.1,590.11 3085.9,649.9 3097.27,649.9 3104.85,642.32 3104.85,630.95 3039.48,565.59 3039.48,544.28 3054.09,529.67 3075.4,529.67 3127.7,581.96 3141.99,581.96 3215.6,508.35 3215.6,368.57 3164,316.97 3164,236.11 3173.84,226.26 3193.7,226.26 3200.7,219.26 v2(3203.11,219.26)
  Bottom Layer w5.9: v2(3203.11,219.26) 3205.32,219.26 3213.42,227.36 3226.87,227.36 3236.26,217.98 R226.2@3236.26,217.48
RADAR_LVDS_CLKP: R225.2 U1.K20 | length 3238.6
  Top Layer w5.8: U1.K20@2290.01,2576.08 2283.76,2569.83 2283.76,2514.59 2345.03,2453.31 2345.03,2411.47 2304,2370.44 2304,2333 2312.63,2324.37 v2(2312.63,2323.45)
  L3_SIG1 w4.8: v2(2312.63,2323.45) 2312.63,2321.19 2305.63,2314.19 2305.63,2245.69 2558.9,1992.42 2558.9,1921.8 2764.23,1716.47 2764.23,973.77 3048.9,689.1 3048.9,667.78 3002.18,621.06 3002.18,609.69 3009.76,602.11 3021.13,602.11 3080.93,661.9 3102.24,661.9 3116.85,647.29 3116.85,625.98 3051.48,560.62 3051.48,549.25 3059.06,541.67 3070.43,541.67 3122.73,593.96 3146.96,593.96 3227.6,513.32 3227.6,363.6 3214.36,350.36 3214.36,343.57 3218.27,339.66 3218.27,331.54 3212.82,326.08 3204.69,326.08 3200.78,330 3193.99,330 3176,312 3176,241.08 3178.81,238.26 3193.7,238.26 3200.7,245.27 v2(3203.11,245.27)
  Bottom Layer w5.9: v2(3203.11,245.27) 3205.32,245.27 3213.42,237.16 3226.74,237.16 3236.26,246.68 R225.2@3236.26,247.17
RADAR_LVDS_FRCLKM: R220.2 U1.M21 | length 3313
  Top Layer w5.8: v2(2201.63,2290.73) 2193,2299.36 2193,2354.17 2211.04,2372.2 2215.84,2372.2 2221.54,2366.51 2227,2366.51 2231.63,2371.13 2231.63,2375.94 2225.6,2381.96 2225.6,2386.77 2274.02,2435.18 2274.02,2493.2 2250.64,2516.58 U1.M21@2250.64,2556.4
  L3_SIG1 w4.8: v2(2201.63,2290.73) 2201.63,2288.32 2194.63,2281.32 2194.63,2275.69 2498.78,1971.54 2498.78,1674.19 2584,1588.97 2584,1373.1 2572.01,1361.11 2538.96,1361.11 2534,1356.15 2534,1341.27 2538.96,1336.31 2619.91,1336.31 2631.9,1324.32 2631.9,1299.5 2619.91,1287.51 2538.96,1287.51 2534,1282.55 2534,1267.67 2538.96,1262.71 2620.61,1262.71 2632.6,1250.72 2632.6,1225.9 2620.61,1213.91 ; 2618.61,1213.91 2536.46,1213.91 2531.5,1208.95 2531.5,1194.07 2536.46,1189.11 2572.01,1189.11 2584,1177.12 2584,1027.24 2900.66,710.58 2907.69,703.55 2907.69,534.81 3145.18,297.32 3145.18,201.75 3152.32,194.61 v2(3152.32,192.33)
  Bottom Layer w5.9: v2(3152.32,192.33) 3152.32,194.27 3143.16,203.44 3143.16,219.04 3152.18,228.06 R220.2@3152.67,228.06
RADAR_LVDS_FRCLKP: R219.2 U1.N20 | length 3315.2
  Top Layer w5.8: v2(2175.63,2290.73) 2175.63,2292.26 2183,2299.63 2183,2358.31 2264.02,2439.32 2264.02,2489.06 2237.75,2515.33 2237.75,2569.28 U1.N20@2230.95,2576.08
  L3_SIG1 w4.8: v2(2175.63,2290.73) 2175.63,2288.32 2182.63,2281.32 2182.63,2270.72 2486.78,1966.57 2486.78,1669.22 2572,1584 2572,1378.07 2567.04,1373.11 2533.99,1373.11 2522,1361.12 2522,1336.3 2533.99,1324.31 2614.94,1324.31 2619.9,1319.35 2619.9,1304.47 2614.94,1299.51 2533.99,1299.51 2522,1287.52 2522,1262.7 2533.99,1250.71 2615.64,1250.71 2620.6,1245.75 2620.6,1230.87 2615.64,1225.91 2531.49,1225.91 2519.5,1213.92 2519.5,1189.1 2531.49,1177.11 2567.04,1177.11 2572,1172.15 2572,1022.27 2895.69,698.58 2895.69,529.84 3133.18,292.35 3133.18,201.75 3126.04,194.61 v2(3126.04,192.33)
  Bottom Layer w5.9: R219.2@3123.48,228.06 3123.97,228.06 3133.36,218.67 3133.36,201.84 3126.04,194.53 v2(3126.04,192.33)
RADAR_nERROR_OUT: D13.1 R247.1 R288.1 R289.2 U1.AA20 U15.13 | length 4217.2
  Top Layer w8: 2027.52,2558.55 2044.32,2575.35 2071.44,2575.35 2071.81,2575.73 2073.12,2575.73 U1.AA20@2073.47,2576.08
  Top Layer w9: U15.13@2268.13,1341.71 2275.14,1341.71 2275.56,1341.29 2275.56,1334.29 2277.89,1331.97 v2(2277.89,1329.53)
  Top Layer w10.8: v2(1130.92,647.22) 1152.69,647.22 1163.39,657.92 D13.1@1163.39,685.39 ; R247.1@1685.11,2293.95 v2(1685.11,2324.4) 1685.11,2425.66 1811.21,2551.75 2020.72,2551.75 2027.52,2558.55
  L3_SIG1 w6: v2(1685.11,2324.4) 1667.41,2342.11 1628.82,2342.11 1585,2298.29 1585,2262.92 1713.37,2134.55 1713.37,2001.63 2115.47,1599.53 2115.47,1480.27 2149,1446.75 2149,1322.59 2219.39,1252.2 ; v2(2219.19,1022.23) 2219.39,1022.43 2219.39,1252.2 ; v2(2277.89,1329.53) 2277.89,1283.14 2246.95,1252.2 2219.39,1252.2
  L6_SIG2 w6: v2(1130.92,647.22) 1278.45,794.75 1435.23,794.75 1491.77,851.29 1491.77,990.06 1536.78,1035.07 1850.93,1035.07 1914,972 2094,972 2144.23,1022.23 v2(2219.19,1022.23)
  Bottom Layer w8: R288.1@2133.08,1269.69 2119.52,1256.14 R289.2@2078.3,1256.14 2078.3,1201.1 2094.61,1184.8 2094.61,1081.79 2154.17,1022.23 v2(2219.19,1022.23)
RADAR_NRST: C134.2 R171.2 R250.1 U1.Y7 U17.4 | length 3709.6
  Top Layer w4: 2037.65,2820.58 2081.74,2820.58 U1.Y7@2093.15,2831.99
  Top Layer w6: U17.4@1068.58,1809.55 1068.58,1824.95 v2(1077.53,1833.9) ; v2(2004.3,2799.75) 2005.82,2799.75 2026.65,2820.58 2037.65,2820.58
  Top Layer w10.8: R250.1@1513.86,2669.49 C134.2@1513.86,2705 v2(1513.86,2732.86) ; R171.2@1789.9,355.83 1789.9,341.48 v2(1802.44,328.94)
  L3_SIG1 w6: v2(1316.85,1875.78) 1316.85,2222.05 1368.29,2273.5 1368.29,2587.29 v2(1513.86,2732.86) 1906.53,2732.86 1973.42,2799.75 v2(2004.3,2799.75) ; v2@1317.42,1875.21 1317.42,1773.57 1339.38,1751.6 1339.38,1426.62 1453,1313 1453,1252.72 1500.62,1205.1 1540.16,1205.1 1741.44,1003.82 1741.44,389.94 v2(1802.44,328.94)
  L6_SIG2 w6: v2(1077.53,1833.9) 1093.88,1850.25 1291.32,1850.25 v2(1316.85,1875.78)
RADAR_NRST_1: D4.2 R63.1 R123.1 R183.2 U17.1 | length 6074.4
  Top Layer w6.5: 1036.65,1755.22 1041.02,1759.59 U17.1@1041.02,1778.05
  Top Layer w10.8: 1036.65,1755.22 1028.35,1746.91 1028.35,1728.79 1032.79,1724.35 1034.76,1724.35 1041.03,1718.08 1051.71,1718.08 v2(1052.53,1717.26) ; v2(1678.08,967.78) 1678.67,968.38 1693.59,968.38 1700.07,961.91 1700.07,953.22 D4.2@1704.02,949.27
  L3_SIG1 w6: v2(1052.53,1717.26) 1068.49,1717.26 1096.87,1688.87 1096.87,1603.5 1219.67,1480.7 1219.67,1101.52 1342.35,978.84 1342.35,924.66 1389.98,877.03 1418.54,877.03 1447.19,848.38 1494.37,848.38 1523.95,877.96 1706.14,877.96 1719.92,891.73 1719.92,942.05 1694.19,967.78 v2(1678.08,967.78) ; v2(2920,1629.36) 2868.38,1577.74 2868.38,1509.62 2975.44,1402.56 2975.44,1181.62 3072.81,1084.25 3113.64,1084.25 3577.89,620 v2(3645,620)
  L6_SIG2 w6: v2(1052.53,1717.26) 1123.15,1717.26 1135.59,1729.69 1331.03,1729.69 1413.73,1646.99 1906.98,1646.99 1970.49,1710.51 2122.14,1710.51 2205.64,1627 2628,1627 2710.6,1709.6 2922.23,1709.6 2945,1686.83 2945,1654.36 v2(2920,1629.36)
  Bottom Layer w6: R63.1@3550.88,620.51 3644.49,620.51 v2(3645,620)
  Bottom Layer w8.7: R183.2@2616.19,1102.8 2659.32,1102.8 2755.12,1198.59 2755.12,1459.59 2723.02,1491.68 2678.16,1491.68 2659.23,1510.62 2659.23,1541.66 2689.03,1571.47 2862.11,1571.47 v2@2916.96,1626.32 ; v2@2918.22,1625.06 2920,1626.85 v2(2920,1629.36)
RADAR_NRST_2: C53.1 R165.1 R243.2 S2.3 S2.4 U17.6 | length 2455.6
  Top Layer w6: v2(1030.25,1835.55) 1041.02,1824.77 U17.6@1041.02,1809.55
  Top Layer w10.8: v2(903.04,820.05) 938.72,784.37 S2.3@943.03,784.37 1004.96,784.37 1054.96,734.37 R165.1@1256.02,734.37 ; C53.1@1256.02,694.37 R165.1@1256.02,734.37 ; v2@1414.3,707.4 1414.3,707.74 1383.82,738.21 1361.5,738.21 1315.34,784.37 S2.4@1256.02,784.37 R165.1@1256.02,734.37
  L3_SIG1 w6: v2(800.4,1825.36) 800.11,1825.07 800.11,1535.66 854.21,1481.56 854.21,1217.51 903.04,1168.67 v2(903.04,820.05)
  L6_SIG2 w6: v2(800.4,1825.36) 1020.06,1825.36 v2(1030.25,1835.55) ; v2(1414.46,707.57) 1471.43,707.57 1503.92,740.06 v2(1849.78,740.06)
  Bottom Layer w8.7: R243.2@1835.71,720.47 1840.71,725.48 1840.71,730.99 v2(1849.78,740.06)
RADAR_OSC_CLKOUT: TP2.1 U1.H8 | length 626
  Top Layer w8: v2@1817,2969 TP2.1@1843,2969 ; U1.H8@2329.38,2812.3 2329.73,2812.65 2329.73,2818.57 2338.45,2827.28 v2(2338.45,2829.35)
  L6_SIG2 w6: v2(1817.11,2969.11) 1941.1,2969.11 2036.2,2874 2293.79,2874 v2(2338.45,2829.35)
RADAR_SYNC_IN_GPIO_5: J15.1 R81.1 U1.Y19 | length 2783.7
  Top Layer w4: v2(2006.75,2595.2) 2007.48,2594.48 2047.09,2594.48 2059.71,2607.1 2081.83,2607.1 U1.Y19@2093.15,2595.77
  Top Layer w10.8: J15.1@536.88,1369.43 566.19,1369.43 641.47,1444.72 v2(641.47,1551.5) ; R81.1@1844.28,2345.91 1844.28,2346.04 1848.23,2349.99 1848.36,2349.99 v2(1866.33,2368.05)
  L3_SIG1 w6: v2(1492.47,1581.91) 1450.63,1623.75 1450.63,1759.64 1569.96,1878.97 1569.96,2309.25 1628.76,2368.05 v2(1866.33,2368.05) 1913.5,2415.22 1913.5,2501.95 v2(2006.75,2595.2)
  L6_SIG2 w6: v2(641.47,1551.5) 641.47,1504.53 695.25,1450.75 744.72,1450.75 855.18,1561.21 948.83,1561.21 1016.05,1628.44 1380.66,1628.44 1427.19,1581.91 v2(1492.47,1581.91)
